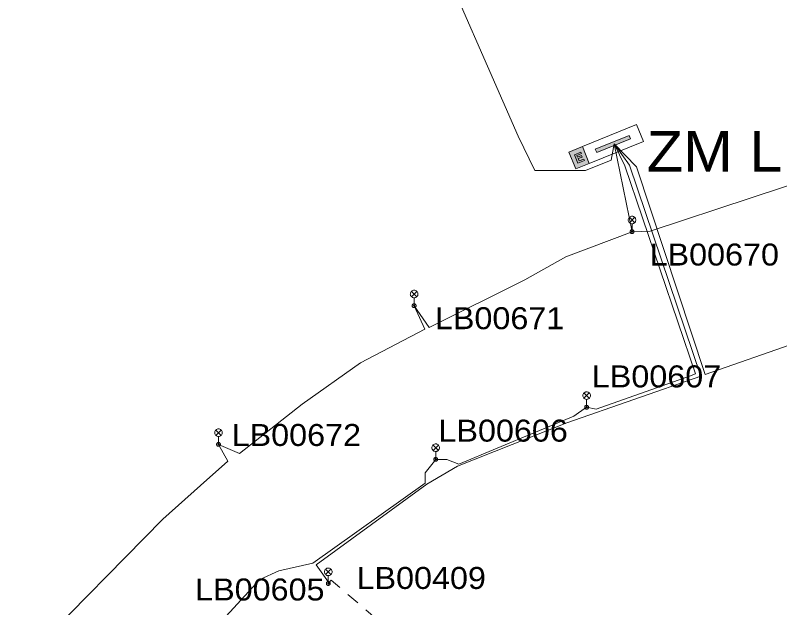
# Model space of a CAD drawing. Extents: x -688049 to -687261, y -973611 to -973038.
# Drawn here: x -687425.6 to -687350.2, y -973470.9 to -973412.5 of the extents above; entities that cross this region are included whole.
import ezdxf

# ---------------------------------------------------------------- set-up
doc = ezdxf.new("R2010")
doc.units = 0
doc.header["$LTSCALE"] = 0.87
doc.linetypes.add('LONG_DASH_SHORT_DASH', pattern=[9.9, 6, -1.2, 1.5, -1.2])
doc.layers.add('1', color=7, linetype='Continuous', lineweight=13)

msp = doc.modelspace()

# ---------------------------------------------------------------- hatches: boundary and pattern name
at = {"layer": '1'}
for points in [[(-687368.385, -973425.67), (-687365.051, -973424.311), (-687364.915, -973424.645), (-687368.249, -973426.003)], [(-687370.99, -973425.954), (-687369.657, -973425.41), (-687368.978, -973427.077), (-687370.311, -973427.621)], [(-687370.111, -973427.053), (-687370.45, -973426.22), (-687369.807, -973425.957), (-687369.751, -973426.096), (-687370.204, -973426.281), (-687370.129, -973426.464), (-687369.736, -973426.304), (-687369.68, -973426.442), (-687370.073, -973426.602), (-687369.983, -973426.824), (-687369.529, -973426.639), (-687369.467, -973426.791)]]:
    msp.add_hatch(color=256, dxfattribs=at).paths.add_polyline_path(points)

# ---------------------------------------------------------------- linework, layer by layer
for p, q in [((-687366.538, -973425.138), (-687364.76, -973433.8)), ((-687365.025, -973432.385), (-687364.495, -973432.915)), ((-687365.025, -973432.915), (-687364.495, -973432.385)), ((-687364.76, -973433.8), (-687364.76, -973433.025)), ((-687386.525, -973439.685), (-687385.995, -973440.215)), ((-687386.525, -973440.215), (-687385.995, -973439.685)), ((-687386.26, -973441.1), (-687386.26, -973440.325)), ((-687369.505, -973449.695), (-687368.975, -973450.225)), ((-687369.505, -973450.225), (-687368.975, -973449.695)), ((-687369.24, -973451.11), (-687369.24, -973450.335)), ((-687405.825, -973453.355), (-687405.295, -973453.885)), ((-687405.825, -973453.885), (-687405.295, -973453.355)), ((-687405.56, -973454.77), (-687405.56, -973453.995)), ((-687384.398, -973454.835), (-687383.868, -973455.365)), ((-687384.398, -973455.365), (-687383.868, -973454.835)), ((-687384.133, -973456.25), (-687384.133, -973455.475)), ((-687394.995, -973467.075), (-687394.465, -973467.605)), ((-687394.995, -973467.605), (-687394.465, -973467.075)), ((-687394.73, -973468.49), (-687394.73, -973467.715))]:
    msp.add_line(p, q, dxfattribs=at)
at = {"layer": '1', "linetype": 'LONG_DASH_SHORT_DASH'}
for p, q in [((-687394.43, -973468.17), (-687394.73, -973468.49)), ((-687367.46, -973491.32), (-687394.43, -973468.17))]:
    msp.add_line(p, q, dxfattribs=at)
at = {"layer": '1'}
for points in [[(-687380.798, -973246.294), (-687379.608, -973246.294), (-687378.955, -973247.562), (-687376.887, -973255.287), (-687406.818, -973265.671), (-687416.352, -973274.485), (-687413.576, -973311.675), (-687413.576, -973319.312), (-687415.981, -973327.719), (-687423.796, -973339.13), (-687419.572, -973351.385), (-687409.434, -973351.385), (-687402.464, -973355.4), (-687399.787, -973359.445), (-687396.201, -973367.518), (-687384.836, -973404.179), (-687376.008, -973424.395), (-687374.353, -973427.776), (-687369.362, -973427.776), (-687366.818, -973426.737), (-687366.538, -973425.138)], [(-687369.657, -973425.41), (-687364.322, -973423.237), (-687363.643, -973424.904), (-687368.978, -973427.077)], [(-687366.538, -973425.138), (-687365.012, -973427.239), (-687357.975, -973448.038), (-687371.194, -973452.656), (-687381.982, -973456.931), (-687385.011, -973458.711), (-687395.909, -973466.654), (-687394.551, -973468.597)], [(-687369.24, -973451.11), (-687368.304, -973451.308), (-687359.09, -973448.048), (-687358.511, -973447.819), (-687365.463, -973427.306), (-687366.538, -973425.138)], [(-687366.538, -973425.138), (-687364.323, -973427.393), (-687357.554, -973447.881), (-687348.508, -973444.739), (-687346.912, -973443.272)], [(-687341.475, -973425.779), (-687343.038, -973427.165), (-687362.968, -973433.766), (-687364.76, -973433.8)], [(-687364.76, -973433.8), (-687371.303, -973436.268), (-687375.332, -973438.56), (-687384.785, -973443.25), (-687386.26, -973441.1)], [(-687386.26, -973441.1), (-687385.207, -973443.408), (-687391.553, -973446.728), (-687397.294, -973450.811), (-687403.482, -973455.685), (-687405.56, -973454.77)], [(-687384.133, -973456.25), (-687383.033, -973456.25), (-687381.86, -973456.71), (-687370.51, -973451.978), (-687369.24, -973451.11)], [(-687405.56, -973454.77), (-687404.641, -973456.423), (-687407.326, -973458.82), (-687411.049, -973462.143), (-687423.916, -973475.233), (-687425.61, -973474.31)], [(-687406.95, -973473.08), (-687405.926, -973472.922), (-687401.497, -973468.097), (-687399.617, -973467.227), (-687396.262, -973466.483), (-687385.16, -973458.6), (-687385.16, -973457.575), (-687384.133, -973456.25)]]:
    msp.add_lwpolyline(points, dxfattribs=at)
for points in [[(-687368.385, -973425.67), (-687365.051, -973424.311), (-687364.915, -973424.645), (-687368.249, -973426.003)], [(-687370.99, -973425.954), (-687369.657, -973425.41), (-687368.978, -973427.077), (-687370.311, -973427.621)], [(-687370.99, -973425.954), (-687369.657, -973425.41), (-687368.978, -973427.077), (-687370.311, -973427.621)], [(-687370.111, -973427.053), (-687370.45, -973426.22), (-687369.807, -973425.957), (-687369.751, -973426.096), (-687370.204, -973426.281), (-687370.129, -973426.464), (-687369.736, -973426.304), (-687369.68, -973426.442), (-687370.073, -973426.602), (-687369.983, -973426.824), (-687369.529, -973426.639), (-687369.467, -973426.791)], [(-687364.385, -973432.65), (-687364.391, -973432.585), (-687364.408, -973432.522), (-687364.435, -973432.462), (-687364.473, -973432.409), (-687364.519, -973432.363), (-687364.572, -973432.325), (-687364.632, -973432.298), (-687364.695, -973432.281), (-687364.76, -973432.275), (-687364.825, -973432.281), (-687364.888, -973432.298), (-687364.948, -973432.325), (-687365.001, -973432.363), (-687365.047, -973432.409), (-687365.085, -973432.462), (-687365.112, -973432.522), (-687365.129, -973432.585), (-687365.135, -973432.65), (-687365.129, -973432.715), (-687365.112, -973432.778), (-687365.085, -973432.838), (-687365.047, -973432.891), (-687365.001, -973432.937), (-687364.948, -973432.975), (-687364.888, -973433.002), (-687364.825, -973433.019), (-687364.76, -973433.025), (-687364.695, -973433.019), (-687364.632, -973433.002), (-687364.572, -973432.975), (-687364.519, -973432.937), (-687364.473, -973432.891), (-687364.435, -973432.838), (-687364.408, -973432.778), (-687364.391, -973432.715)], [(-687364.57, -973433.8), (-687364.573, -973433.767), (-687364.581, -973433.735), (-687364.595, -973433.705), (-687364.614, -973433.678), (-687364.638, -973433.654), (-687364.665, -973433.635), (-687364.695, -973433.621), (-687364.727, -973433.613), (-687364.76, -973433.61), (-687364.793, -973433.613), (-687364.825, -973433.621), (-687364.855, -973433.635), (-687364.882, -973433.654), (-687364.906, -973433.678), (-687364.925, -973433.705), (-687364.939, -973433.735), (-687364.947, -973433.767), (-687364.95, -973433.8), (-687364.947, -973433.833), (-687364.939, -973433.865), (-687364.925, -973433.895), (-687364.906, -973433.922), (-687364.882, -973433.946), (-687364.855, -973433.965), (-687364.825, -973433.979), (-687364.793, -973433.987), (-687364.76, -973433.99), (-687364.727, -973433.987), (-687364.695, -973433.979), (-687364.665, -973433.965), (-687364.638, -973433.946), (-687364.614, -973433.922), (-687364.595, -973433.895), (-687364.581, -973433.865), (-687364.573, -973433.833)], [(-687364.71, -973433.8), (-687364.711, -973433.791), (-687364.713, -973433.783), (-687364.717, -973433.775), (-687364.722, -973433.768), (-687364.728, -973433.762), (-687364.735, -973433.757), (-687364.743, -973433.753), (-687364.751, -973433.751), (-687364.76, -973433.75), (-687364.769, -973433.751), (-687364.777, -973433.753), (-687364.785, -973433.757), (-687364.792, -973433.762), (-687364.798, -973433.768), (-687364.803, -973433.775), (-687364.807, -973433.783), (-687364.809, -973433.791), (-687364.81, -973433.8), (-687364.809, -973433.809), (-687364.807, -973433.817), (-687364.803, -973433.825), (-687364.798, -973433.832), (-687364.792, -973433.838), (-687364.785, -973433.843), (-687364.777, -973433.847), (-687364.769, -973433.849), (-687364.76, -973433.85), (-687364.751, -973433.849), (-687364.743, -973433.847), (-687364.735, -973433.843), (-687364.728, -973433.838), (-687364.722, -973433.832), (-687364.717, -973433.825), (-687364.713, -973433.817), (-687364.711, -973433.809)], [(-687385.885, -973439.95), (-687385.891, -973439.885), (-687385.908, -973439.822), (-687385.935, -973439.763), (-687385.973, -973439.709), (-687386.019, -973439.663), (-687386.072, -973439.625), (-687386.132, -973439.598), (-687386.195, -973439.581), (-687386.26, -973439.575), (-687386.325, -973439.581), (-687386.388, -973439.598), (-687386.448, -973439.625), (-687386.501, -973439.663), (-687386.547, -973439.709), (-687386.585, -973439.763), (-687386.612, -973439.822), (-687386.629, -973439.885), (-687386.635, -973439.95), (-687386.629, -973440.015), (-687386.612, -973440.078), (-687386.585, -973440.138), (-687386.547, -973440.191), (-687386.501, -973440.237), (-687386.448, -973440.275), (-687386.388, -973440.302), (-687386.325, -973440.319), (-687386.26, -973440.325), (-687386.195, -973440.319), (-687386.132, -973440.302), (-687386.072, -973440.275), (-687386.019, -973440.237), (-687385.973, -973440.191), (-687385.935, -973440.138), (-687385.908, -973440.078), (-687385.891, -973440.015)], [(-687386.07, -973441.1), (-687386.073, -973441.067), (-687386.081, -973441.035), (-687386.095, -973441.005), (-687386.114, -973440.978), (-687386.138, -973440.954), (-687386.165, -973440.935), (-687386.195, -973440.921), (-687386.227, -973440.913), (-687386.26, -973440.91), (-687386.293, -973440.913), (-687386.325, -973440.921), (-687386.355, -973440.935), (-687386.382, -973440.954), (-687386.406, -973440.978), (-687386.425, -973441.005), (-687386.439, -973441.035), (-687386.447, -973441.067), (-687386.45, -973441.1), (-687386.447, -973441.133), (-687386.439, -973441.165), (-687386.425, -973441.195), (-687386.406, -973441.222), (-687386.382, -973441.246), (-687386.355, -973441.265), (-687386.325, -973441.279), (-687386.293, -973441.287), (-687386.26, -973441.29), (-687386.227, -973441.287), (-687386.195, -973441.279), (-687386.165, -973441.265), (-687386.138, -973441.246), (-687386.114, -973441.222), (-687386.095, -973441.195), (-687386.081, -973441.165), (-687386.073, -973441.133)], [(-687386.21, -973441.1), (-687386.211, -973441.091), (-687386.213, -973441.083), (-687386.217, -973441.075), (-687386.222, -973441.068), (-687386.228, -973441.062), (-687386.235, -973441.057), (-687386.243, -973441.053), (-687386.251, -973441.051), (-687386.26, -973441.05), (-687386.269, -973441.051), (-687386.277, -973441.053), (-687386.285, -973441.057), (-687386.292, -973441.062), (-687386.298, -973441.068), (-687386.303, -973441.075), (-687386.307, -973441.083), (-687386.309, -973441.091), (-687386.31, -973441.1), (-687386.309, -973441.109), (-687386.307, -973441.117), (-687386.303, -973441.125), (-687386.298, -973441.132), (-687386.292, -973441.138), (-687386.285, -973441.143), (-687386.277, -973441.147), (-687386.269, -973441.149), (-687386.26, -973441.15), (-687386.251, -973441.149), (-687386.243, -973441.147), (-687386.235, -973441.143), (-687386.228, -973441.138), (-687386.222, -973441.132), (-687386.217, -973441.125), (-687386.213, -973441.117), (-687386.211, -973441.109)], [(-687368.865, -973449.96), (-687368.871, -973449.895), (-687368.888, -973449.832), (-687368.915, -973449.772), (-687368.953, -973449.719), (-687368.999, -973449.673), (-687369.052, -973449.635), (-687369.112, -973449.608), (-687369.175, -973449.591), (-687369.24, -973449.585), (-687369.305, -973449.591), (-687369.368, -973449.608), (-687369.428, -973449.635), (-687369.481, -973449.673), (-687369.527, -973449.719), (-687369.565, -973449.772), (-687369.592, -973449.832), (-687369.609, -973449.895), (-687369.615, -973449.96), (-687369.609, -973450.025), (-687369.592, -973450.088), (-687369.565, -973450.148), (-687369.527, -973450.201), (-687369.481, -973450.247), (-687369.428, -973450.285), (-687369.368, -973450.312), (-687369.305, -973450.329), (-687369.24, -973450.335), (-687369.175, -973450.329), (-687369.112, -973450.312), (-687369.052, -973450.285), (-687368.999, -973450.247), (-687368.953, -973450.201), (-687368.915, -973450.148), (-687368.888, -973450.088), (-687368.871, -973450.025)], [(-687369.05, -973451.11), (-687369.053, -973451.077), (-687369.061, -973451.045), (-687369.075, -973451.015), (-687369.094, -973450.988), (-687369.118, -973450.964), (-687369.145, -973450.945), (-687369.175, -973450.931), (-687369.207, -973450.923), (-687369.24, -973450.92), (-687369.273, -973450.923), (-687369.305, -973450.931), (-687369.335, -973450.945), (-687369.362, -973450.964), (-687369.386, -973450.988), (-687369.405, -973451.015), (-687369.419, -973451.045), (-687369.427, -973451.077), (-687369.43, -973451.11), (-687369.427, -973451.143), (-687369.419, -973451.175), (-687369.405, -973451.205), (-687369.386, -973451.232), (-687369.362, -973451.256), (-687369.335, -973451.275), (-687369.305, -973451.289), (-687369.273, -973451.297), (-687369.24, -973451.3), (-687369.207, -973451.297), (-687369.175, -973451.289), (-687369.145, -973451.275), (-687369.118, -973451.256), (-687369.094, -973451.232), (-687369.075, -973451.205), (-687369.061, -973451.175), (-687369.053, -973451.143)], [(-687369.19, -973451.11), (-687369.191, -973451.101), (-687369.193, -973451.093), (-687369.197, -973451.085), (-687369.202, -973451.078), (-687369.208, -973451.072), (-687369.215, -973451.067), (-687369.223, -973451.063), (-687369.231, -973451.061), (-687369.24, -973451.06), (-687369.249, -973451.061), (-687369.257, -973451.063), (-687369.265, -973451.067), (-687369.272, -973451.072), (-687369.278, -973451.078), (-687369.283, -973451.085), (-687369.287, -973451.093), (-687369.289, -973451.101), (-687369.29, -973451.11), (-687369.289, -973451.119), (-687369.287, -973451.127), (-687369.283, -973451.135), (-687369.278, -973451.142), (-687369.272, -973451.148), (-687369.265, -973451.153), (-687369.257, -973451.157), (-687369.249, -973451.159), (-687369.24, -973451.16), (-687369.231, -973451.159), (-687369.223, -973451.157), (-687369.215, -973451.153), (-687369.208, -973451.148), (-687369.202, -973451.142), (-687369.197, -973451.135), (-687369.193, -973451.127), (-687369.191, -973451.119)], [(-687405.185, -973453.62), (-687405.191, -973453.555), (-687405.208, -973453.492), (-687405.235, -973453.432), (-687405.273, -973453.379), (-687405.319, -973453.333), (-687405.372, -973453.295), (-687405.432, -973453.268), (-687405.495, -973453.251), (-687405.56, -973453.245), (-687405.625, -973453.251), (-687405.688, -973453.268), (-687405.748, -973453.295), (-687405.801, -973453.333), (-687405.847, -973453.379), (-687405.885, -973453.432), (-687405.912, -973453.492), (-687405.929, -973453.555), (-687405.935, -973453.62), (-687405.929, -973453.685), (-687405.912, -973453.748), (-687405.885, -973453.808), (-687405.847, -973453.861), (-687405.801, -973453.907), (-687405.748, -973453.945), (-687405.688, -973453.972), (-687405.625, -973453.989), (-687405.56, -973453.995), (-687405.495, -973453.989), (-687405.432, -973453.972), (-687405.372, -973453.945), (-687405.319, -973453.907), (-687405.273, -973453.861), (-687405.235, -973453.808), (-687405.208, -973453.748), (-687405.191, -973453.685)], [(-687405.37, -973454.77), (-687405.373, -973454.737), (-687405.381, -973454.705), (-687405.395, -973454.675), (-687405.414, -973454.648), (-687405.438, -973454.624), (-687405.465, -973454.605), (-687405.495, -973454.591), (-687405.527, -973454.583), (-687405.56, -973454.58), (-687405.593, -973454.583), (-687405.625, -973454.591), (-687405.655, -973454.605), (-687405.682, -973454.624), (-687405.706, -973454.648), (-687405.725, -973454.675), (-687405.739, -973454.705), (-687405.747, -973454.737), (-687405.75, -973454.77), (-687405.747, -973454.803), (-687405.739, -973454.835), (-687405.725, -973454.865), (-687405.706, -973454.892), (-687405.682, -973454.916), (-687405.655, -973454.935), (-687405.625, -973454.949), (-687405.593, -973454.957), (-687405.56, -973454.96), (-687405.527, -973454.957), (-687405.495, -973454.949), (-687405.465, -973454.935), (-687405.438, -973454.916), (-687405.414, -973454.892), (-687405.395, -973454.865), (-687405.381, -973454.835), (-687405.373, -973454.803)], [(-687405.51, -973454.77), (-687405.511, -973454.761), (-687405.513, -973454.753), (-687405.517, -973454.745), (-687405.522, -973454.738), (-687405.528, -973454.732), (-687405.535, -973454.727), (-687405.543, -973454.723), (-687405.551, -973454.721), (-687405.56, -973454.72), (-687405.569, -973454.721), (-687405.577, -973454.723), (-687405.585, -973454.727), (-687405.592, -973454.732), (-687405.598, -973454.738), (-687405.603, -973454.745), (-687405.607, -973454.753), (-687405.609, -973454.761), (-687405.61, -973454.77), (-687405.609, -973454.779), (-687405.607, -973454.787), (-687405.603, -973454.795), (-687405.598, -973454.802), (-687405.592, -973454.808), (-687405.585, -973454.813), (-687405.577, -973454.817), (-687405.569, -973454.819), (-687405.56, -973454.82), (-687405.551, -973454.819), (-687405.543, -973454.817), (-687405.535, -973454.813), (-687405.528, -973454.808), (-687405.522, -973454.802), (-687405.517, -973454.795), (-687405.513, -973454.787), (-687405.511, -973454.779)], [(-687383.758, -973455.1), (-687383.764, -973455.035), (-687383.781, -973454.972), (-687383.808, -973454.913), (-687383.846, -973454.859), (-687383.892, -973454.813), (-687383.946, -973454.775), (-687384.005, -973454.748), (-687384.068, -973454.731), (-687384.133, -973454.725), (-687384.198, -973454.731), (-687384.261, -973454.748), (-687384.32, -973454.775), (-687384.374, -973454.813), (-687384.42, -973454.859), (-687384.458, -973454.913), (-687384.485, -973454.972), (-687384.502, -973455.035), (-687384.508, -973455.1), (-687384.502, -973455.165), (-687384.485, -973455.228), (-687384.458, -973455.288), (-687384.42, -973455.341), (-687384.374, -973455.387), (-687384.32, -973455.425), (-687384.261, -973455.452), (-687384.198, -973455.469), (-687384.133, -973455.475), (-687384.068, -973455.469), (-687384.005, -973455.452), (-687383.946, -973455.425), (-687383.892, -973455.387), (-687383.846, -973455.341), (-687383.808, -973455.288), (-687383.781, -973455.228), (-687383.764, -973455.165)], [(-687383.943, -973456.25), (-687383.946, -973456.217), (-687383.954, -973456.185), (-687383.968, -973456.155), (-687383.987, -973456.128), (-687384.011, -973456.104), (-687384.038, -973456.085), (-687384.068, -973456.071), (-687384.1, -973456.063), (-687384.133, -973456.06), (-687384.166, -973456.063), (-687384.198, -973456.071), (-687384.228, -973456.085), (-687384.255, -973456.104), (-687384.279, -973456.128), (-687384.298, -973456.155), (-687384.312, -973456.185), (-687384.32, -973456.217), (-687384.323, -973456.25), (-687384.32, -973456.283), (-687384.312, -973456.315), (-687384.298, -973456.345), (-687384.279, -973456.372), (-687384.255, -973456.396), (-687384.228, -973456.415), (-687384.198, -973456.429), (-687384.166, -973456.437), (-687384.133, -973456.44), (-687384.1, -973456.437), (-687384.068, -973456.429), (-687384.038, -973456.415), (-687384.011, -973456.396), (-687383.987, -973456.372), (-687383.968, -973456.345), (-687383.954, -973456.315), (-687383.946, -973456.283)], [(-687384.083, -973456.25), (-687384.084, -973456.241), (-687384.086, -973456.233), (-687384.09, -973456.225), (-687384.095, -973456.218), (-687384.101, -973456.212), (-687384.108, -973456.207), (-687384.116, -973456.203), (-687384.124, -973456.201), (-687384.133, -973456.2), (-687384.142, -973456.201), (-687384.15, -973456.203), (-687384.158, -973456.207), (-687384.165, -973456.212), (-687384.171, -973456.218), (-687384.176, -973456.225), (-687384.18, -973456.233), (-687384.182, -973456.241), (-687384.183, -973456.25), (-687384.182, -973456.259), (-687384.18, -973456.267), (-687384.176, -973456.275), (-687384.171, -973456.282), (-687384.165, -973456.288), (-687384.158, -973456.293), (-687384.15, -973456.297), (-687384.142, -973456.299), (-687384.133, -973456.3), (-687384.124, -973456.299), (-687384.116, -973456.297), (-687384.108, -973456.293), (-687384.101, -973456.288), (-687384.095, -973456.282), (-687384.09, -973456.275), (-687384.086, -973456.267), (-687384.084, -973456.259)], [(-687394.355, -973467.34), (-687394.361, -973467.275), (-687394.378, -973467.212), (-687394.405, -973467.153), (-687394.443, -973467.099), (-687394.489, -973467.053), (-687394.542, -973467.015), (-687394.602, -973466.988), (-687394.665, -973466.971), (-687394.73, -973466.965), (-687394.795, -973466.971), (-687394.858, -973466.988), (-687394.918, -973467.015), (-687394.971, -973467.053), (-687395.017, -973467.099), (-687395.055, -973467.153), (-687395.082, -973467.212), (-687395.099, -973467.275), (-687395.105, -973467.34), (-687395.099, -973467.405), (-687395.082, -973467.468), (-687395.055, -973467.528), (-687395.017, -973467.581), (-687394.971, -973467.627), (-687394.918, -973467.665), (-687394.858, -973467.692), (-687394.795, -973467.709), (-687394.73, -973467.715), (-687394.665, -973467.709), (-687394.602, -973467.692), (-687394.542, -973467.665), (-687394.489, -973467.627), (-687394.443, -973467.581), (-687394.405, -973467.528), (-687394.378, -973467.468), (-687394.361, -973467.405)], [(-687394.54, -973468.49), (-687394.543, -973468.457), (-687394.551, -973468.425), (-687394.565, -973468.395), (-687394.584, -973468.368), (-687394.608, -973468.344), (-687394.635, -973468.325), (-687394.665, -973468.311), (-687394.697, -973468.303), (-687394.73, -973468.3), (-687394.763, -973468.303), (-687394.795, -973468.311), (-687394.825, -973468.325), (-687394.852, -973468.344), (-687394.876, -973468.368), (-687394.895, -973468.395), (-687394.909, -973468.425), (-687394.917, -973468.457), (-687394.92, -973468.49), (-687394.917, -973468.523), (-687394.909, -973468.555), (-687394.895, -973468.585), (-687394.876, -973468.612), (-687394.852, -973468.636), (-687394.825, -973468.655), (-687394.795, -973468.669), (-687394.763, -973468.677), (-687394.73, -973468.68), (-687394.697, -973468.677), (-687394.665, -973468.669), (-687394.635, -973468.655), (-687394.608, -973468.636), (-687394.584, -973468.612), (-687394.565, -973468.585), (-687394.551, -973468.555), (-687394.543, -973468.523)], [(-687394.68, -973468.49), (-687394.681, -973468.481), (-687394.683, -973468.473), (-687394.687, -973468.465), (-687394.692, -973468.458), (-687394.698, -973468.452), (-687394.705, -973468.447), (-687394.713, -973468.443), (-687394.721, -973468.441), (-687394.73, -973468.44), (-687394.739, -973468.441), (-687394.747, -973468.443), (-687394.755, -973468.447), (-687394.762, -973468.452), (-687394.768, -973468.458), (-687394.773, -973468.465), (-687394.777, -973468.473), (-687394.779, -973468.481), (-687394.78, -973468.49), (-687394.779, -973468.499), (-687394.777, -973468.507), (-687394.773, -973468.515), (-687394.768, -973468.522), (-687394.762, -973468.528), (-687394.755, -973468.533), (-687394.747, -973468.537), (-687394.739, -973468.539), (-687394.73, -973468.54), (-687394.721, -973468.539), (-687394.713, -973468.537), (-687394.705, -973468.533), (-687394.698, -973468.528), (-687394.692, -973468.522), (-687394.687, -973468.515), (-687394.683, -973468.507), (-687394.681, -973468.499)]]:
    msp.add_lwpolyline(points, close=True, dxfattribs=at)

# ---------------------------------------------------------------- texts
at = {"layer": '1', "width": 1.1}
for s, height, p in [('ZM LB086', 4, (-687363.322, -973427.883)), ('LB00670', 2.167, (-687363.027, -973437.139)), ('LB00671', 2.167, (-687384.208, -973443.416)), ('LB00607', 2.167, (-687368.729, -973449.152)), ('LB00606', 2.167, (-687383.86, -973454.501)), ('LB00672', 2.167, (-687404.264, -973454.93)), ('LB00409', 2.167, (-687391.941, -973469.027)), ('LB00605', 2.167, (-687407.865, -973470.164))]:
    msp.add_text(s, height=height, dxfattribs=at).set_placement(p)

doc.saveas('drawing.dxf')
